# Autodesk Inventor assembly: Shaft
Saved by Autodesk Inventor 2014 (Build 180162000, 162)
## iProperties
Created: 2010-12
Part Number: Shaft
Document SubType Name: Assembly
Designer: Thom Tremblay
ClientObjectVersion: 1
Author: Thom Tremblay
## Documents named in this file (2)
- C:\Inventor 2014 Essentials\Assemblies\Chapter 08\c08-01\Design Accelerator\Shaft6.iam
- C:\Inventor 2014 Essentials\Assemblies\Chapter 08\c08-01\Design Accelerator\Shaft6.ipt
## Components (1 placed, 1 different names)
1. Shaft:1
